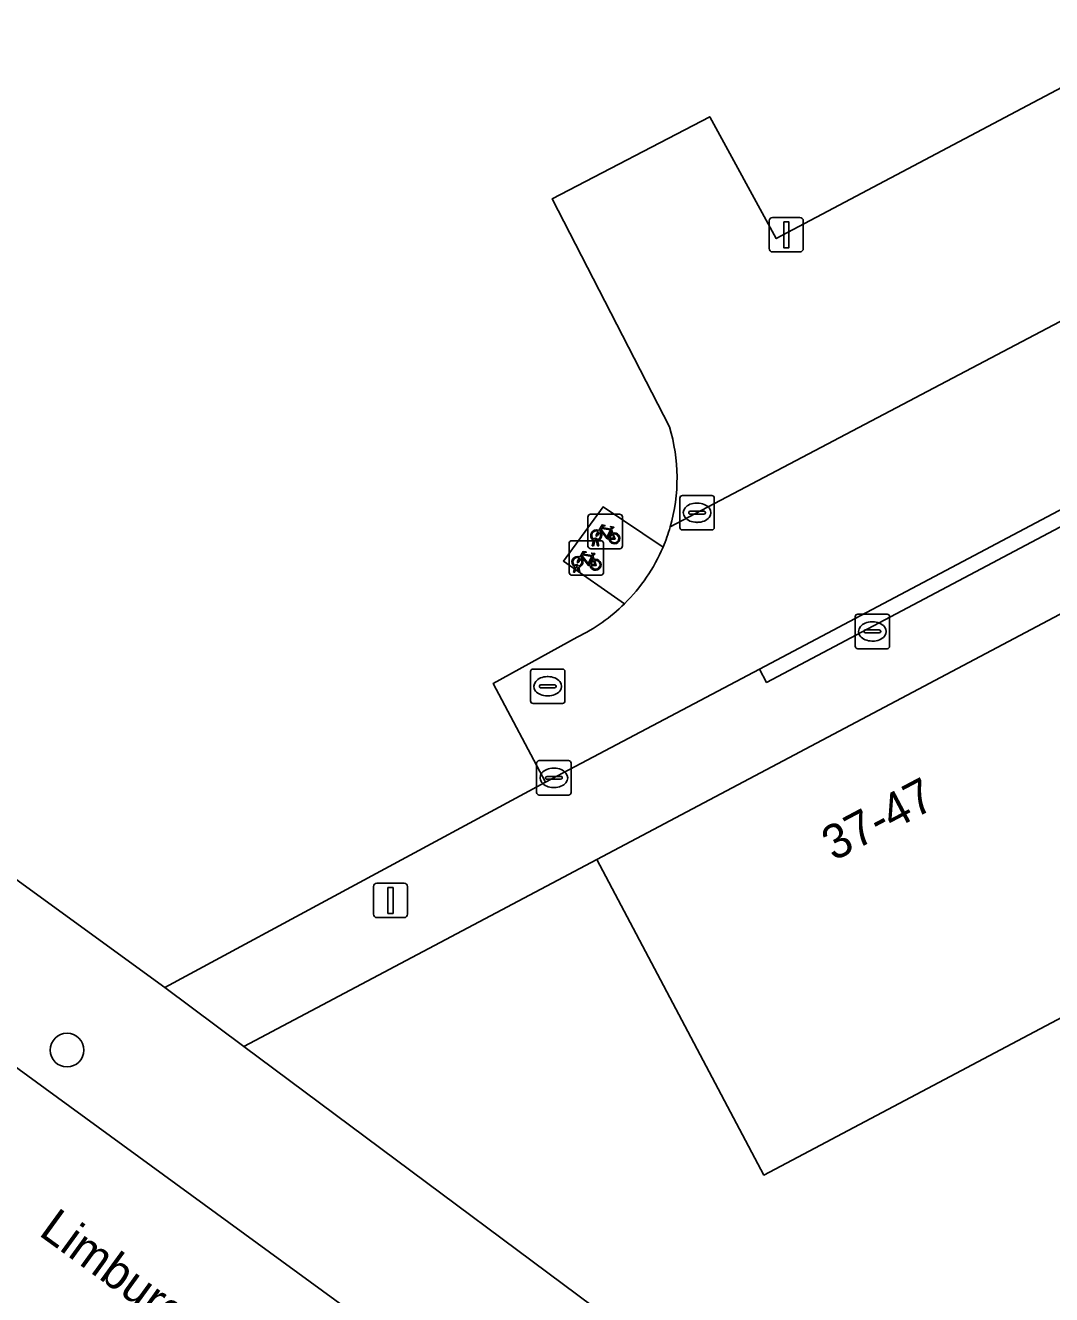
# Model space of a CAD drawing. Extents: x 159674 to 160531, y 382172 to 382904.
# Drawn here: x 159999.42 to 160029.22, y 382265.94 to 382302.8 of the extents above; entities that cross this region are included whole.
import ezdxf

# ---------------------------------------------------------------- set-up
doc = ezdxf.new("R2010")
doc.units = 0
for name, color, linetype in [('IMGEO_Boom', 7, 'Continuous'), ('IMGEO_Brandkraan', 7, 'Continuous'), ('IMGEO_Erf', 7, 'Continuous'), ('IMGEO_Fietsenrek', 7, 'Continuous'), ('IMGEO_Groenvoorziening', 7, 'Continuous'), ('IMGEO_Kolk', 7, 'Continuous'), ('IMGEO_Lichtmast', 7, 'Continuous'), ('IMGEO_Openbare_ruimte_label', 7, 'Continuous'), ('IMGEO_Pand', 7, 'Continuous'), ('IMGEO_Pand_nummerreeks', 7, 'Continuous'), ('IMGEO_Parkeervlak_open', 7, 'Continuous'), ('IMGEO_Rijbaan_lokaal_open', 7, 'Continuous'), ('IMGEO_Rioolput', 7, 'Continuous'), ('IMGEO_Terreindeel_open', 7, 'Continuous'), ('IMGEO_Voetpad_open', 7, 'Continuous')]:
    doc.layers.add(name, color=color, linetype=linetype)

msp = doc.modelspace()

# ---------------------------------------------------------------- linework, layer by layer
at = {"layer": 'IMGEO_Boom'}
msp.add_circle((160000.632, 382273.037), 0.489, dxfattribs=at)
at = {"layer": 'IMGEO_Brandkraan'}
for p, q in [((160023.592, 382285.696), (160024.444, 382285.696)), ((160023.517, 382284.77), (160023.517, 382285.622)), ((160024.005, 382285.476), (160024.03, 382285.476)), ((160024.518, 382285.622), (160024.518, 382284.77)), ((160023.776, 382285.19), (160023.776, 382285.202)), ((160024.214, 382285.153), (160023.816, 382285.153)), ((160023.819, 382285.239), (160024.217, 382285.239)), ((160024.26, 382285.202), (160024.26, 382285.19)), ((160024.444, 382284.696), (160023.592, 382284.696)), ((160024.028, 382284.916), (160024.003, 382284.916))]:
    msp.add_line(p, q, dxfattribs=at)
for points in [[(160023.592, 382285.696), (160024.444, 382285.696)], [(160023.517, 382284.77), (160023.517, 382285.622)], [(160024.518, 382285.622), (160024.518, 382284.77)], [(160024.444, 382284.696), (160023.592, 382284.696)]]:
    msp.add_lwpolyline(points, dxfattribs=at)
for centre, radius, start, end in [((160023.594, 382285.62), 0.0765, 91.552, 178.448), ((160023.594, 382285.62), 0.0765, 91.552, 178.448), ((160024.442, 382285.62), 0.0765, 1.552, 88.448), ((160024.442, 382285.62), 0.0765, 1.552, 88.448), ((160023.816, 382285.199), 0.0403, 85.8775, 175.7526), ((160023.813, 382285.189), 0.0366, 178.938, 274.7102), ((160024.217, 382285.196), 0.043, 264.8664, 352.4533), ((160024.221, 382285.201), 0.0386, 1.7309, 96.639), ((160023.594, 382284.772), 0.0765, 181.552, 268.448), ((160023.594, 382284.772), 0.0765, 181.552, 268.448), ((160024.442, 382284.772), 0.0765, 271.552, 358.448), ((160024.442, 382284.772), 0.0765, 271.552, 358.448)]:
    msp.add_arc(centre, radius, start, end, dxfattribs=at)
for centre, major_axis, ratio, start_param, end_param in [((160024.004, 382285.196), (-0.387, 0.002), 0.722429, 4.712389, 7.853982), ((160024.029, 382285.196), (-0.39, 0.002), 0.717154, 1.570796, 4.712389)]:
    msp.add_ellipse(centre, major_axis=major_axis, ratio=ratio, start_param=start_param, end_param=end_param, dxfattribs=at)
at = {"layer": 'IMGEO_Erf'}
msp.add_lwpolyline([(160086.028, 382319.631), (160083.339, 382319.397), (160078.204, 382311.499), (160083.057, 382302.331), (160067.532, 382294.112), (160051.977, 382285.878), (160036.422, 382277.643), (160020.867, 382269.409), (160016.014, 382278.577), (160005.765, 382273.145), (160019.447, 382262.957), (160024.762, 382259.009)], dxfattribs=at)
at = {"layer": 'IMGEO_Fietsenrek'}
for p, q in [((160015.759, 382287.675), (160015.759, 382288.516)), ((160015.759, 382288.516), (160015.759, 382287.675)), ((160015.834, 382288.6), (160016.675, 382288.6)), ((160016.675, 382288.6), (160015.834, 382288.6)), ((160016.759, 382288.525), (160016.759, 382287.684)), ((160016.759, 382287.684), (160016.759, 382288.525)), ((160016.446, 382288.149), (160016.482, 382288.054)), ((160015.213, 382286.906), (160015.213, 382287.747)), ((160015.213, 382287.747), (160015.213, 382286.906)), ((160015.288, 382287.831), (160016.129, 382287.831)), ((160016.129, 382287.831), (160015.288, 382287.831)), ((160016.684, 382287.6), (160015.843, 382287.6)), ((160015.843, 382287.6), (160016.684, 382287.6)), ((160015.886, 382287.684), (160015.925, 382287.844)), ((160015.92, 382287.684), (160015.886, 382287.684)), ((160015.955, 382287.832), (160015.92, 382287.684)), ((160015.997, 382287.856), (160015.996, 382287.86)), ((160016.038, 382287.684), (160016.004, 382287.826)), ((160016.028, 382287.867), (160016.029, 382287.86)), ((160016.036, 382287.83), (160016.071, 382287.684)), ((160016.071, 382287.684), (160016.038, 382287.684)), ((160016.213, 382287.756), (160016.213, 382286.915)), ((160016.213, 382286.915), (160016.213, 382287.756)), ((160015.9, 382287.38), (160015.936, 382287.285)), ((160016.138, 382286.831), (160015.297, 382286.831)), ((160015.297, 382286.831), (160016.138, 382286.831)), ((160015.34, 382286.915), (160015.379, 382287.075)), ((160015.374, 382286.915), (160015.34, 382286.915)), ((160015.409, 382287.063), (160015.374, 382286.915)), ((160015.451, 382287.087), (160015.45, 382287.091)), ((160015.492, 382286.915), (160015.458, 382287.057)), ((160015.482, 382287.098), (160015.483, 382287.091)), ((160015.49, 382287.061), (160015.525, 382286.915)), ((160015.525, 382286.915), (160015.492, 382286.915))]:
    msp.add_line(p, q, dxfattribs=at)
for points in [[(160016.072, 382288.126), (160016.167, 382288.29), (160016.253, 382288.276), (160016.255, 382288.267), (160016.199, 382288.256), (160016.172, 382288.211), (160016.428, 382288.17)], [(160016.093, 382288.074), (160016.041, 382287.984), (160016.001, 382287.959), (160016.002, 382288.006), (160016.057, 382288.1)], [(160016.368, 382287.882), (160016.318, 382287.882), (160016.127, 382288.133), (160016.108, 382288.101)], [(160016.415, 382288.145), (160016.158, 382288.186), (160016.141, 382288.157), (160016.308, 382287.937), (160016.415, 382288.145)], [(160016.463, 382288.047), (160016.433, 382288.124), (160016.324, 382287.906), (160016.367, 382287.906)], [(160016.397, 382287.906), (160016.517, 382287.905), (160016.473, 382288.019)], [(160016.493, 382288.026), (160016.548, 382287.881), (160016.398, 382287.881)], [(160016.428, 382288.17), (160016.453, 382288.219), (160016.447, 382288.223), (160016.424, 382288.227), (160016.412, 382288.234), (160016.411, 382288.237), (160016.413, 382288.242), (160016.508, 382288.227), (160016.51, 382288.217), (160016.5, 382288.204), (160016.488, 382288.198), (160016.474, 382288.204), (160016.446, 382288.149)], [(160015.547, 382287.305), (160015.495, 382287.215), (160015.455, 382287.19), (160015.456, 382287.237), (160015.511, 382287.331)], [(160015.526, 382287.357), (160015.621, 382287.521), (160015.707, 382287.507), (160015.709, 382287.498), (160015.653, 382287.487), (160015.626, 382287.442), (160015.882, 382287.401)], [(160015.822, 382287.113), (160015.772, 382287.113), (160015.581, 382287.364), (160015.562, 382287.332)], [(160015.869, 382287.376), (160015.612, 382287.417), (160015.595, 382287.388), (160015.762, 382287.168), (160015.869, 382287.376)], [(160015.917, 382287.278), (160015.887, 382287.355), (160015.778, 382287.137), (160015.821, 382287.137)], [(160015.851, 382287.137), (160015.971, 382287.136), (160015.927, 382287.25)], [(160015.947, 382287.257), (160016.002, 382287.112), (160015.852, 382287.112)], [(160015.882, 382287.401), (160015.907, 382287.45), (160015.901, 382287.454), (160015.878, 382287.458), (160015.866, 382287.465), (160015.865, 382287.468), (160015.867, 382287.473), (160015.962, 382287.458), (160015.964, 382287.448), (160015.954, 382287.435), (160015.942, 382287.429), (160015.928, 382287.435), (160015.9, 382287.38)]]:
    msp.add_lwpolyline(points, dxfattribs=at)
for centre, radius, start, end in [((160015.837, 382288.522), 0.0779, 92.4484, 184.2845), ((160015.837, 382288.522), 0.0779, 92.4484, 184.2845), ((160016.681, 382288.522), 0.0779, 2.4484, 94.2845), ((160016.681, 382288.522), 0.0779, 2.4484, 94.2845), ((160015.999, 382287.985), 0.159, 62.6766, 242.1369), ((160015.999, 382287.985), 0.129, 63.3192, 238.903), ((160015.979, 382287.856), 0.0499, 12.8025, 158.6934), ((160015.999, 382287.985), 0.129, 283.6043, 43.4302), ((160015.999, 382287.985), 0.159, 283.5766, 46.6042), ((160016.526, 382287.901), 0.159, 113.3408, 178.3217), ((160016.526, 382287.901), 0.159, 187.0065, 105.7708), ((160016.526, 382287.901), 0.129, 113.923, 177.9556), ((160016.526, 382287.901), 0.129, 188.6715, 104.5883), ((160015.291, 382287.753), 0.0779, 92.4484, 184.2845), ((160015.291, 382287.753), 0.0779, 92.4484, 184.2845), ((160015.837, 382287.678), 0.0779, 182.4484, 274.2845), ((160015.837, 382287.678), 0.0779, 182.4484, 274.2845), ((160015.999, 382287.985), 0.159, 253.9967, 271.7867), ((160015.979, 382287.856), 0.0174, 12.8025, 163.4502), ((160015.999, 382287.985), 0.129, 253.415, 269.0204), ((160016.135, 382287.753), 0.0779, 2.4484, 94.2845), ((160016.135, 382287.753), 0.0779, 2.4484, 94.2845), ((160016.681, 382287.678), 0.0779, 272.4484, 4.2845), ((160016.681, 382287.678), 0.0779, 272.4484, 4.2845), ((160015.453, 382287.216), 0.159, 62.6766, 242.1369), ((160015.453, 382287.216), 0.129, 63.3192, 238.903), ((160015.453, 382287.216), 0.129, 283.6043, 43.4302), ((160015.453, 382287.216), 0.159, 283.5766, 46.6042), ((160015.98, 382287.132), 0.159, 113.3408, 178.3217), ((160015.98, 382287.132), 0.159, 187.0065, 105.7708), ((160015.98, 382287.132), 0.129, 113.923, 177.9556), ((160015.98, 382287.132), 0.129, 188.6715, 104.5883), ((160015.291, 382286.909), 0.0779, 182.4484, 274.2845), ((160015.291, 382286.909), 0.0779, 182.4484, 274.2845), ((160015.433, 382287.087), 0.0499, 12.8025, 158.6934), ((160015.453, 382287.216), 0.159, 253.9967, 271.7867), ((160015.433, 382287.087), 0.0174, 12.8025, 163.4502), ((160015.453, 382287.216), 0.129, 253.415, 269.0204), ((160016.135, 382286.909), 0.0779, 272.4484, 4.2845), ((160016.135, 382286.909), 0.0779, 272.4484, 4.2845)]:
    msp.add_arc(centre, radius, start, end, dxfattribs=at)
at = {"layer": 'IMGEO_Groenvoorziening'}
for points in [[(160069.876, 382317.999), (160071.602, 382320.568), (160072.224, 382321.861), (160072.647, 382323.232), (160045.381, 382343.017), (160039.422, 382339.84), (160044.297, 382330.659), (160028.751, 382322.408), (160013.206, 382314.156), (160000, 382307.147), (159997.66, 382305.905), (159982.114, 382297.653), (159977.237, 382306.837), (159966.979, 382301.422), (160000, 382277.384), (160003.473, 382274.856), (160014.527, 382280.815), (160013.011, 382283.689), (160015.445, 382285.033)], [(160018.125, 382291.137), (160014.717, 382297.759), (160019.298, 382300.144), (160021.227, 382296.604), (160032.183, 382302.405), (160033.862, 382299.135)], [(160016.822, 382286.001), (160015.045, 382287.238), (160016.198, 382288.812), (160017.939, 382287.646)]]:
    msp.add_lwpolyline(points, dxfattribs=at)
for centre, radius, start, end in [((160013.262, 382289.65), 5.085, 343.7922, 16.9964), ((160013.348, 382289.592), 4.987, 337.0356, 344.1663), ((160013.241, 382289.632), 5.1, 295.6076, 314.6051)]:
    msp.add_arc(centre, radius, start, end, dxfattribs=at)
at = {"layer": 'IMGEO_Kolk'}
for p, q in [((160018.427, 382288.219), (160018.427, 382289.071)), ((160018.502, 382289.145), (160019.354, 382289.145)), ((160019.428, 382289.071), (160019.428, 382288.219)), ((160018.686, 382288.639), (160018.686, 382288.651)), ((160018.729, 382288.688), (160019.127, 382288.688)), ((160018.915, 382288.925), (160018.94, 382288.925)), ((160019.17, 382288.651), (160019.17, 382288.639)), ((160019.124, 382288.602), (160018.726, 382288.602)), ((160018.938, 382288.365), (160018.913, 382288.365)), ((160019.354, 382288.145), (160018.502, 382288.145)), ((160014.269, 382280.519), (160014.269, 382281.371)), ((160014.344, 382281.445), (160015.196, 382281.445)), ((160015.27, 382281.371), (160015.27, 382280.519)), ((160014.528, 382280.939), (160014.528, 382280.951)), ((160014.966, 382280.902), (160014.568, 382280.902)), ((160014.571, 382280.988), (160014.969, 382280.988)), ((160014.757, 382281.225), (160014.782, 382281.225)), ((160015.012, 382280.951), (160015.012, 382280.939)), ((160014.78, 382280.665), (160014.755, 382280.665)), ((160015.196, 382280.445), (160014.344, 382280.445))]:
    msp.add_line(p, q, dxfattribs=at)
for points in [[(160018.427, 382288.219), (160018.427, 382289.071)], [(160018.502, 382289.145), (160019.354, 382289.145)], [(160019.428, 382289.071), (160019.428, 382288.219)], [(160019.354, 382288.145), (160018.502, 382288.145)], [(160014.269, 382280.519), (160014.269, 382281.371)], [(160014.344, 382281.445), (160015.196, 382281.445)], [(160015.27, 382281.371), (160015.27, 382280.519)], [(160015.196, 382280.445), (160014.344, 382280.445)]]:
    msp.add_lwpolyline(points, dxfattribs=at)
for centre, radius, start, end in [((160018.504, 382289.069), 0.0765, 91.552, 178.448), ((160018.504, 382289.069), 0.0765, 91.552, 178.448), ((160019.352, 382289.069), 0.0765, 1.552, 88.448), ((160019.352, 382289.069), 0.0765, 1.552, 88.448), ((160018.726, 382288.648), 0.0403, 85.8775, 175.7526), ((160018.723, 382288.638), 0.0366, 178.938, 274.7102), ((160019.127, 382288.645), 0.043, 264.8664, 352.4533), ((160019.131, 382288.65), 0.0386, 1.7309, 96.639), ((160018.504, 382288.221), 0.0765, 181.552, 268.448), ((160018.504, 382288.221), 0.0765, 181.552, 268.448), ((160019.352, 382288.221), 0.0765, 271.552, 358.448), ((160019.352, 382288.221), 0.0765, 271.552, 358.448), ((160014.346, 382281.369), 0.0765, 91.552, 178.448), ((160014.346, 382281.369), 0.0765, 91.552, 178.448), ((160015.194, 382281.369), 0.0765, 1.552, 88.448), ((160015.194, 382281.369), 0.0765, 1.552, 88.448), ((160014.568, 382280.948), 0.0403, 85.8775, 175.7526), ((160014.565, 382280.938), 0.0366, 178.938, 274.7102), ((160014.969, 382280.945), 0.043, 264.8664, 352.4533), ((160014.973, 382280.95), 0.0386, 1.7309, 96.639), ((160014.346, 382280.521), 0.0765, 181.552, 268.448), ((160014.346, 382280.521), 0.0765, 181.552, 268.448), ((160015.194, 382280.521), 0.0765, 271.552, 358.448), ((160015.194, 382280.521), 0.0765, 271.552, 358.448)]:
    msp.add_arc(centre, radius, start, end, dxfattribs=at)
for centre, major_axis, ratio, start_param, end_param in [((160018.914, 382288.645), (-0.387, 0.002), 0.722429, 4.712389, 7.853982), ((160018.939, 382288.645), (-0.39, 0.002), 0.717154, 1.570796, 4.712389), ((160014.756, 382280.945), (-0.387, 0.002), 0.722429, 4.712389, 7.853982), ((160014.781, 382280.945), (-0.39, 0.002), 0.717154, 1.570796, 4.712389)]:
    msp.add_ellipse(centre, major_axis=major_axis, ratio=ratio, start_param=start_param, end_param=end_param, dxfattribs=at)
at = {"layer": 'IMGEO_Lichtmast'}
for p, q in [((160021.023, 382296.317), (160021.023, 382297.117)), ((160021.023, 382297.117), (160021.023, 382296.317)), ((160021.123, 382297.217), (160021.913, 382297.217)), ((160021.913, 382297.217), (160021.123, 382297.217)), ((160022.013, 382297.117), (160022.013, 382296.317)), ((160022.013, 382296.317), (160022.013, 382297.117)), ((160021.913, 382296.217), (160021.123, 382296.217)), ((160021.123, 382296.217), (160021.913, 382296.217)), ((160009.531, 382276.984), (160009.531, 382277.784)), ((160009.531, 382277.784), (160009.531, 382276.984)), ((160009.631, 382277.884), (160010.421, 382277.884)), ((160010.421, 382277.884), (160009.631, 382277.884)), ((160010.521, 382277.784), (160010.521, 382276.984)), ((160010.521, 382276.984), (160010.521, 382277.784)), ((160010.421, 382276.884), (160009.631, 382276.884)), ((160009.631, 382276.884), (160010.421, 382276.884))]:
    msp.add_line(p, q, dxfattribs=at)
for points in [[(160021.443, 382297.092), (160021.593, 382297.092), (160021.593, 382296.342), (160021.443, 382296.342), (160021.443, 382297.092)], [(160009.951, 382277.759), (160010.101, 382277.759), (160010.101, 382277.009), (160009.951, 382277.009), (160009.951, 382277.759)]]:
    msp.add_lwpolyline(points, dxfattribs=at)
for centre, start, end in [((160021.123, 382297.117), 90, 180), ((160021.123, 382297.117), 90, 180), ((160021.913, 382297.117), 0, 90), ((160021.913, 382297.117), 360, 90), ((160021.123, 382296.317), 180, 270), ((160021.123, 382296.317), 180, 270), ((160021.913, 382296.317), 270, 0), ((160021.913, 382296.317), 270, 0), ((160009.631, 382277.784), 90, 180), ((160009.631, 382277.784), 90, 180), ((160010.421, 382277.784), 0, 90), ((160010.421, 382277.784), 360, 90), ((160009.631, 382276.984), 180, 270), ((160009.631, 382276.984), 180, 270), ((160010.421, 382276.984), 270, 0), ((160010.421, 382276.984), 270, 0)]:
    msp.add_arc(centre, 0.1, start, end, dxfattribs=at)
at = {"layer": 'IMGEO_Pand'}
msp.add_lwpolyline([(160031.569, 382286.811), (160016.014, 382278.577), (160020.867, 382269.409), (160036.422, 382277.643)], close=True, dxfattribs=at)
at = {"layer": 'IMGEO_Parkeervlak_open'}
for points in [[(160033.862, 382299.135), (160032.183, 382302.405), (160021.227, 382296.604), (160019.298, 382300.144), (160014.717, 382297.759), (160018.125, 382291.137)], [(160018.145, 382288.231), (160037.122, 382298.226)]]:
    msp.add_lwpolyline(points, dxfattribs=at)
msp.add_arc((160013.262, 382289.65), 5.085, 343.7922, 16.9964, dxfattribs=at)
at = {"layer": 'IMGEO_Rijbaan_lokaal_open'}
for points in [[(160062.919, 382311.947), (160057.989, 382309.325), (160056.153, 382308.348), (160037.122, 382298.226), (160018.145, 382288.231)], [(160017.531, 382259.139), (160015.743, 382260.43), (160000, 382271.92), (159982.528, 382284.68), (159953.332, 382305.907)], [(160015.445, 382285.033), (160013.011, 382283.689), (160014.527, 382280.815), (160020.74, 382284.104), (160038.601, 382293.559)]]:
    msp.add_lwpolyline(points, dxfattribs=at)
for centre, radius, start, end in [((160013.348, 382289.592), 4.987, 337.0356, 344.1663), ((160013.215, 382289.652), 5.132, 314.6531, 336.9918), ((160013.241, 382289.632), 5.1, 295.6076, 314.6051)]:
    msp.add_arc(centre, radius, start, end, dxfattribs=at)
at = {"layer": 'IMGEO_Rioolput'}
for p, q in [((160014.089, 382283.178), (160014.089, 382284.03)), ((160014.164, 382284.104), (160015.016, 382284.104)), ((160014.577, 382283.884), (160014.602, 382283.884)), ((160015.09, 382284.03), (160015.09, 382283.178)), ((160014.348, 382283.598), (160014.348, 382283.61)), ((160014.786, 382283.561), (160014.388, 382283.561)), ((160014.391, 382283.647), (160014.789, 382283.647)), ((160014.832, 382283.61), (160014.832, 382283.598)), ((160015.016, 382283.104), (160014.164, 382283.104)), ((160014.6, 382283.324), (160014.575, 382283.324))]:
    msp.add_line(p, q, dxfattribs=at)
for points in [[(160014.089, 382283.178), (160014.089, 382284.03)], [(160014.164, 382284.104), (160015.016, 382284.104)], [(160015.09, 382284.03), (160015.09, 382283.178)], [(160015.016, 382283.104), (160014.164, 382283.104)]]:
    msp.add_lwpolyline(points, dxfattribs=at)
for centre, radius, start, end in [((160014.166, 382284.028), 0.0765, 91.552, 178.448), ((160014.166, 382284.028), 0.0765, 91.552, 178.448), ((160015.014, 382284.028), 0.0765, 1.552, 88.448), ((160015.014, 382284.028), 0.0765, 1.552, 88.448), ((160014.388, 382283.607), 0.0403, 85.8775, 175.7526), ((160014.385, 382283.597), 0.0366, 178.938, 274.7102), ((160014.789, 382283.604), 0.043, 264.8664, 352.4533), ((160014.793, 382283.609), 0.0386, 1.7309, 96.639), ((160014.166, 382283.18), 0.0765, 181.552, 268.448), ((160014.166, 382283.18), 0.0765, 181.552, 268.448), ((160015.014, 382283.18), 0.0765, 271.552, 358.448), ((160015.014, 382283.18), 0.0765, 271.552, 358.448)]:
    msp.add_arc(centre, radius, start, end, dxfattribs=at)
for centre, major_axis, ratio, start_param, end_param in [((160014.576, 382283.604), (-0.387, 0.002), 0.722429, 4.712389, 7.853982), ((160014.601, 382283.604), (-0.39, 0.002), 0.717154, 1.570796, 4.712389)]:
    msp.add_ellipse(centre, major_axis=major_axis, ratio=ratio, start_param=start_param, end_param=end_param, dxfattribs=at)
at = {"layer": 'IMGEO_Terreindeel_open'}
msp.add_lwpolyline([(160017.939, 382287.646), (160016.198, 382288.812), (160015.045, 382287.238), (160016.822, 382286.001)], dxfattribs=at)
msp.add_arc((160013.215, 382289.652), 5.132, 314.6531, 336.9918, dxfattribs=at)
at = {"layer": 'IMGEO_Voetpad_open'}
for points in [[(159887.605, 382353.798), (159890.6, 382351.611), (159893.393, 382349.55), (159896.667, 382347.174), (159905.175, 382340.999), (159920.932, 382329.502), (159937.537, 382317.412), (159953.332, 382305.907), (159982.528, 382284.68), (160000, 382271.92), (160015.743, 382260.43), (160017.531, 382259.139)], [(160024.762, 382259.009), (160019.447, 382262.957), (160005.765, 382273.145), (160003.473, 382274.856), (160000, 382277.384), (159966.979, 382301.422), (159964.599, 382303.191), (159949.672, 382314.284)], [(160070.385, 382311.081), (160070.878, 382310.15), (160053.641, 382301.024), (160053.435, 382301.412), (160038.601, 382293.559), (160038.806, 382293.171), (160020.946, 382283.715), (160020.74, 382284.104), (160014.527, 382280.815), (160003.473, 382274.856), (160005.765, 382273.145), (160016.014, 382278.577), (160031.569, 382286.811), (160047.124, 382295.046), (160062.679, 382303.28)]]:
    msp.add_lwpolyline(points, dxfattribs=at)
msp.add_lwpolyline([(160038.601, 382293.559), (160020.74, 382284.104), (160020.946, 382283.715), (160038.806, 382293.171)], close=True, dxfattribs=at)

# ---------------------------------------------------------------- texts
at = {"layer": 'IMGEO_Openbare_ruimte_label'}
msp.add_text('Limburglaan', height=1, rotation=324.0358, dxfattribs=at).set_placement((159999.778, 382267.683))
at = {"layer": 'IMGEO_Pand_nummerreeks'}
msp.add_text('37-47', height=1, rotation=27.8957, dxfattribs=at).set_placement((160022.899, 382278.511))

doc.saveas('drawing.dxf')
